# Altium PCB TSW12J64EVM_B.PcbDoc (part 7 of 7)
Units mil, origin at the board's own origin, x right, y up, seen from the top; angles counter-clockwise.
Board outline 8833 x 2680 mil, 10 copper layers (Top Layer L1, Gnd-Plane - L2, Signals - L3, Gnd-Plane - L4, Pwr Plane - L5, Signals - L6, Gnd-Plane - L7, Signals - L8, Gnd-Plane - L9, Bottom Layer - L10), stack 57.8 mil thick; 950 components, 533 nets, 2888 pads, 1732 vias.
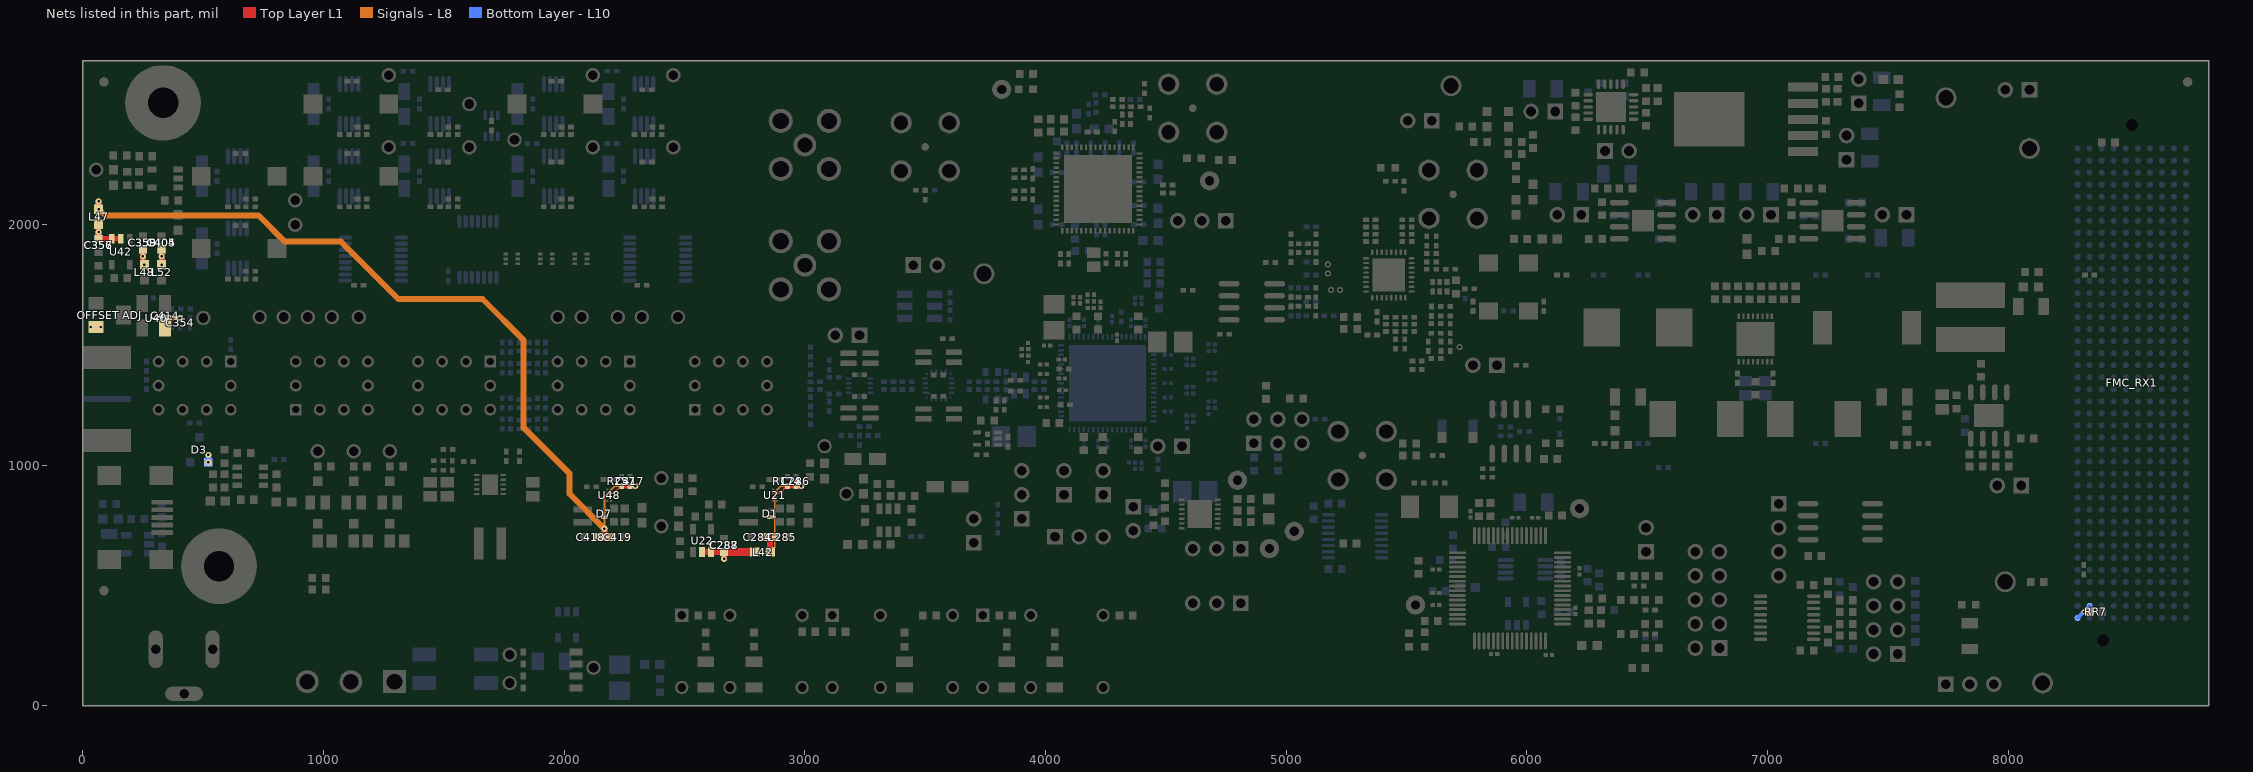
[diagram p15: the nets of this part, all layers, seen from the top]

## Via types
v1: diameter 18, hole 8, Top Layer L1 to Bottom Layer - L10, tented both sides, 1096 vias
v2: diameter 21.46, hole 10, Top Layer L1 to Bottom Layer - L10, tented both sides, 266 vias
v3: diameter 25, hole 10, Top Layer L1 to Bottom Layer - L10, tented both sides, 154 vias
v4: diameter 19.68, hole 7.87, Top Layer L1 to Bottom Layer - L10, 103 vias
v5: diameter 18, hole 8, Top Layer L1 to Bottom Layer - L10, tented bottom, 42 vias
v6: diameter 18, hole 8, Top Layer L1 to Bottom Layer - L10, tented top, 24 vias
v7: diameter 18, hole 8.01, Top Layer L1 to Bottom Layer - L10, tented both sides, 16 vias
v8: diameter 18, hole 8.01, Top Layer L1 to Bottom Layer - L10, tented bottom, 16 vias
v9: diameter 25.98, hole 12.99, Top Layer L1 to Bottom Layer - L10, tented top, 8 vias
v10: diameter 19.68, hole 7.87, Top Layer L1 to Bottom Layer - L10, tented top, 5 vias
v11: diameter 126, hole 106, Top Layer L1 to Bottom Layer - L10, tented top, 2 vias

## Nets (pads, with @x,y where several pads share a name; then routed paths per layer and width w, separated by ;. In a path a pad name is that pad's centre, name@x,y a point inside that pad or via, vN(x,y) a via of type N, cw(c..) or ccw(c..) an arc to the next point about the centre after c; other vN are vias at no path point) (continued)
VIO_-3: C404.1 C405.1 D3.1 L52.2 | length 155.5
  Top Layer L1 w24: v3(328,1832.91) v3(328,1867.4) C405.1@328,1895.65
  Bottom Layer - L10 w24: v3(328,1832.91) v3(328,1867.4) C404.1@328,1895.65
  Bottom Layer - L10 w25: v3(522.18,1012.5) v3(522.18,1042.5)
VIO_-3_LMH: "OFFSET ADJ.3" C354.1 C358.1 C359.1 C414.2 L48.2 U40.2 | length 268.1
  Top Layer L1 w21.46: C414.2@342,1569.82 360.6,1588.42 v2(360.6,1611) v2(405,1611)
  Top Layer L1 w24: C359.1@250,1895.65 v3(250,1867.4) 250,1838.9 v3(255.99,1832.91)
  Bottom Layer - L10 w15.75: v2(360.6,1611) v2(405,1611)
  Bottom Layer - L10 w24: C358.1@250,1895.65 v3(250,1867.4) 250,1838.9 v3(255.99,1832.91)
  other v2: 34.15,1573.79 75.68,1573.79
VIO_-3P25_1: C287.1 C288.1 L42.2 U22.2 U22.3 | length 276.5
  Top Layer L1 w24: v3(2665,610.51) C288.1@2665,638.76
  Top Layer L1 w25: U22.2@2573,638.76 U22.3@2610.4,638.76 C288.1@2665,638.76
  Top Layer L1 w31.5: C288.1@2665,638.76 L42.2@2793,638.76
  Bottom Layer - L10 w24: v3(2665,610.51) C287.1@2665,638.76
VIO_-3P25_2: C356.1 C357.1 L47.2 U42.2 U42.3 | length 180.7
  Top Layer L1 w23.62: C357.1@66,1940.13 U42.3@120.6,1940.13 U42.2@158,1940.13
  Top Layer L1 w24: C357.1@66,1940.13 v3(66,1968.38) L47.2@66,2000.57
  Bottom Layer - L10 w24: C356.1@66,1940.13 v3(66,1968.38)
VIO_-3P25V_1: C284.2 C285.2 C286.1 D1.2 L42.1 R174.2 U21.B2 | length 600.3
  Top Layer L1 w8: U21.B2@2883.86,882.9 2895.86,882.9 2925.3,912.34 R174.2@2927.99,912.34
  Top Layer L1 w19: R174.2@2927.99,912.34 C286.1@2962.99,912.34 v3(2985.33,912.34)
  Top Layer L1 w25: v3(2855.99,638.76) 2855.99,701.02
  Top Layer L1 w31.5: C284.2@2832.55,701.02 2855.99,701.02 C285.2@2879.43,701.02
  Signals - L8 w8: v3(2855.99,638.76) 2875,657.77 2875,888 2899.34,912.34 v3(2985.33,912.34)
VIO_-3P25V_2: C417.1 C418.2 C419.2 D7.2 L47.1 R257.2 U48.B2 | length 3463.1
  Top Layer L1 w8: U48.B2@2194.86,882.9 2206.86,882.9 2236.3,912.34 R257.2@2238.99,912.34
  Top Layer L1 w19: R257.2@2238.99,912.34 C417.1@2273.99,912.34 v3(2296.33,912.34)
  Top Layer L1 w24: v3(66,2063.56) v3(66,2095.74)
  Top Layer L1 w31.5: C418.2@2138.74,701.02 v3(2166.99,701.02) C419.2@2195.24,701.02
  Signals - L8 w8: v3(2166.99,736.02) 2166.99,868.99 2210.34,912.34 v3(2296.33,912.34)
  Signals - L8 w25: v3(66,2095.74) v3(66,2063.56) 92.56,2037 731,2037 840,1928 1073,1928 1311,1690 1661,1690 1832,1519 1832,1155 2023,964 2023,880.01 v3(2166.99,736.02) v3(2166.99,701.02)
VIO_B_M2C_RX: FMC_RX1.J39 FMC_RX1.K40 RR7.2 | length 93.2
  Top Layer L1 w18: v1(8313,390) RR7.2@8335.44,390
  Bottom Layer - L10 w18: FMC_RX1.K40@8288,365 v1(8313,390) FMC_RX1.J39@8338,415
pads on no net: 5VDC.3 "SH-Ts ADD1_1_2.0" FID1.1 FID2.1 FID3.1 FMC_RX1.401 FMC_RX1.402 FMC_RX1.A22 FMC_RX1.A23 FMC_RX1.A26 FMC_RX1.A27 FMC_RX1.A30 FMC_RX1.A31 FMC_RX1.A34 FMC_RX1.A35 FMC_RX1.A38 FMC_RX1.A39 FMC_RX1.B1 FMC_RX1.B4 FMC_RX1.B5 FMC_RX1.B8 FMC_RX1.B9 FMC_RX1.B20 FMC_RX1.B21 FMC_RX1.B24 FMC_RX1.B25 FMC_RX1.B28 FMC_RX1.B29 FMC_RX1.B32 FMC_RX1.B33 FMC_RX1.B36 FMC_RX1.B37 FMC_RX1.B40 FMC_RX1.C2 FMC_RX1.C3 FMC_RX1.C10 FMC_RX1.C11 FMC_RX1.C14 FMC_RX1.C15 FMC_RX1.C18 FMC_RX1.C19 FMC_RX1.C22 FMC_RX1.C23 FMC_RX1.C26 FMC_RX1.C27 FMC_RX1.D8 FMC_RX1.D9 FMC_RX1.D11 FMC_RX1.D12 FMC_RX1.D14 FMC_RX1.D15 FMC_RX1.D17 FMC_RX1.D18 FMC_RX1.D20 FMC_RX1.D21 FMC_RX1.D23 FMC_RX1.D24 FMC_RX1.D27 FMC_RX1.D29 FMC_RX1.D33 FMC_RX1.D34 FMC_RX1.E2 FMC_RX1.E3 FMC_RX1.E6 FMC_RX1.E7 FMC_RX1.E9 FMC_RX1.E10 FMC_RX1.E15 FMC_RX1.E16 FMC_RX1.E18 FMC_RX1.E19 FMC_RX1.E21 FMC_RX1.E22 FMC_RX1.E24 FMC_RX1.E25 FMC_RX1.E27 FMC_RX1.E28 FMC_RX1.E30 FMC_RX1.E31 FMC_RX1.E33 FMC_RX1.E34 FMC_RX1.E37 FMC_RX1.F4 FMC_RX1.F5 FMC_RX1.F7 FMC_RX1.F8 FMC_RX1.F10 FMC_RX1.F11 FMC_RX1.F13 FMC_RX1.F14 FMC_RX1.F16 FMC_RX1.F17 FMC_RX1.F19 FMC_RX1.F20 FMC_RX1.F22 FMC_RX1.F23 FMC_RX1.F25 FMC_RX1.F26 FMC_RX1.F28 FMC_RX1.F29 FMC_RX1.F31 FMC_RX1.F32 FMC_RX1.F34 FMC_RX1.F35 FMC_RX1.F37 FMC_RX1.F38 FMC_RX1.G2 FMC_RX1.G3 FMC_RX1.G15 FMC_RX1.G16 FMC_RX1.G18 FMC_RX1.G19 FMC_RX1.G21 FMC_RX1.G22 FMC_RX1.G24 FMC_RX1.G25 FMC_RX1.G28 FMC_RX1.G31 FMC_RX1.H1 FMC_RX1.H4 FMC_RX1.H5 FMC_RX1.H7 FMC_RX1.H8 FMC_RX1.H10 FMC_RX1.H11 FMC_RX1.H13 FMC_RX1.H14 FMC_RX1.H16 FMC_RX1.H17 FMC_RX1.H19 FMC_RX1.H20 FMC_RX1.H22 FMC_RX1.H23 FMC_RX1.H25 FMC_RX1.H26 FMC_RX1.H28 FMC_RX1.H29 FMC_RX1.H32 FMC_RX1.H35 FMC_RX1.J2 FMC_RX1.J3 FMC_RX1.J6 FMC_RX1.J7 FMC_RX1.J9 FMC_RX1.J10 FMC_RX1.J12 FMC_RX1.J13 FMC_RX1.J18 FMC_RX1.J19 FMC_RX1.J21 FMC_RX1.J22 FMC_RX1.J24 FMC_RX1.J25 FMC_RX1.J27 FMC_RX1.J28 FMC_RX1.J30 FMC_RX1.J31 FMC_RX1.J33 FMC_RX1.J34 FMC_RX1.J36 FMC_RX1.J37 FMC_RX1.K1 FMC_RX1.K4 FMC_RX1.K5 FMC_RX1.K7 FMC_RX1.K8 FMC_RX1.K10 FMC_RX1.K11 FMC_RX1.K13 FMC_RX1.K14 FMC_RX1.K16 FMC_RX1.K17 FMC_RX1.K19 FMC_RX1.K20 FMC_RX1.K22 FMC_RX1.K23 FMC_RX1.K25 FMC_RX1.K26 FMC_RX1.K31 FMC_RX1.K32 FMC_RX1.K34 FMC_RX1.K35 H3.0 H4.0 H5.1 H6.1 S1.3 SH-1V2ADC_INT_1_2.0 SH-1V2ADC_LDO_1_2.0 SH-1V9ADC_1_2.0 SH-1V9INT_1_2.0 SH-EXT5V_FMC12V_1_2.0 SH-FTDI_3P3V_1_2.0 SH-J2_1_2.0 SH-LMK_INT_1_2.0 SH-LMK_LDO_1_2.0 SH-LMX_INT_1_2.0 SH-LMX_LDO_1_2.0 SH-RSV_1_2.0 U3.1 U3.3 U3.4 U5.2 U5.7 U8.2 U8.7 U10.2 U10.3 U10.4 U10.9 U10.13 U10.14 U10.17 U13.21 U13.22 U13.23 U13.24 U13.30 U13.32 U13.33 U13.34 U13.36 U13.44 U13.45 U13.46 U13.55 U13.57 U13.58 U13.59 U13.60 U15.6 U15.7 U16.7 U17.4 U23. U27.10 U27.11 U29.10 U29.11 U40.3 U47.1 U47.3 USB.4 uWIRE.1 uWIRE.3 uWIRE.5 uWIRE.7 Vcmo_2_3.0
copper on no net:
  other v11: 8434,100 8434,2580

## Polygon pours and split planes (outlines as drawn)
VIO_3P3V_LMK_PLL on Signals - L8 "Signals - L8-VIO_3P3V_LMK_PLL" (solid, pour order 213): 4202,1924 4262,1924 4262,1995 4297,2030 4380,2030 4380,2277 6060,2277 6060,2353 4380,2353 4380,2497 4055,2497 4055,1974 4202,1974
VIO_3P3V_LMK_CLK on Signals - L8 "Signals - L8-VIO_3P3V_LMK_CLK" (solid, pour order 219): 4615,2153 6185,2153 6185,2661 3925,2660 3925,1871 4030,1871 4030,2522 4405,2522 4405,2378 6085,2378 6085,2252 4404,2252 4404,2025 4517,2025 4517,2097 4494,2097 4494,2197 4571,2197
VIO_4P05V on Signals - L3 "Signals - L3-VIO_4P05V" (solid, pour order 235): 8063,1400 8063,1695 6024,1695 6024,1400
VIO_1P9V on Signals - L3 "Signals - L3-VIO_1P9V" (solid, remove dead copper, pour order 211): 3991,2660 7554,2660 7554,2094 5866,2094 5866,2285 5533,2285 5533,2094 4213,2094 4213,1592 4290,1592 4290,944 4189,944 4189,1046 3863,1046 3863,1164 3991,1164
3P3V_FTDI on Signals - L3 "Signals - L3-3P3V_FTDI" (solid, remove dead copper, pour order 218): 4678,572 5163,572 5163,883 5452,883 5452,970 5739,970 5739,888 6211.89,887.9 6338.9,760.89 6339,476 6247,476 6247,451 5807,451 5807,540 6119,540 6119,793 6060,793 6060,739 5807,739 5807,783 5723,783 5723,451 5634,451 5634,377 6247,377 6247,476 6339,476 6339,389 6254,304 6253.9,167.11 6166.89,80.1 5777.11,80.1 5654,203 5513.21,203 5452.1,264.11 5452.1,443 4744,443 4744,393 4678,393
1P8V_USB on Signals - L3 "Signals - L3-1P8V_USB" (solid, remove dead copper, pour order 220): 5644,387 5644,441 5733,441 5733,773 5797,773 5797,729 6070,729 6070,783 6109,783 6109,550 5797,550 5797,441 6237,441 6237,387
VIO_3P3V_LMX on Signals - L3 "Signals - L3 - VIO_3P3V_LMX" (solid, remove dead copper, pour order 230): 5792,2043 5497,2043 5497,1954 5551,1954 5551,1777 5792,1777
VIO_3P3V_LMX on Signals - L3 "Signals - L3- VIO_3P3V_LMX" (solid, remove dead copper, pour order 229): 4942,2043 5355,2043 5355,1954 5071,1954 5071,1777 4942,1777
VIO_4P05V on Signals - L3 "Signals - L3-VIO_4P05V" (solid, remove dead copper, pour order 234): 4315,1366 4315,930 4164,930 4164,1032 3822,1032 3822,1884 2968,1884 2968,1129 1364,1129 1364,889 672,889 672,816 901,587 5098,587 5098,1366
3P3V_USB on Signals - L3 "Signals - L3-3P3V_USB" (solid, remove dead copper, pour order 217): 20,1029.9 401.03,1029.9 401.03,842.97 436,808 665,808 901,572 4644,572 4644,393 4579,393 4579,443 926,443 633,736 493,736 401.03,644.03 400.94,535.1 20,535.1
GND on Bottom Layer - L10 "Bottom Layer - L10-T2-GND" (solid, pour order 209): 3314,1545 3663,1545 3663,1574 3492,1574 3492,1645 3573,1645 3573,1675 3492,1675 3492,1745.91 3663,1745.91 3663,1774.91 3314,1774.91
GND on Bottom Layer - L10 "Bottom Layer - L10-U10-GND" (solid, pour order 208): 6285,2426 6421,2426 6421,2550 6285,2550 6270,2565 6238,2565 6238,2530 6285,2483
GND on Bottom Layer - L10 "Bottom Layer - L10-U6-GND" (solid, pour order 210): 4055,1989 4106,1989 4106,1978 4140,1978 4140,1985 4380,1985 4380,2310 4079,2310 4079,2305 4031,2305 4031,2273 4055,2273
5P0_12P0V_INT on Bottom Layer - L10 "Bottom Layer L10-12P0_INT" (solid, pour order 190): 6984,1405 6914,1405 6914,1327 6984,1327 6984,1405
GND on Bottom Layer - L10 "Bottom Layer L10-GND" (solid, pour order 224): 4980,2000 4980,1834 5097,1834 5097,2000
GND on Bottom Layer - L10 "Bottom Layer L10 - U4 G ND" (solid, pour order 223): 5357.34,1858.9 5357.34,1721.1 5495.13,1721.1 5495.13,1858.9
GND on Bottom Layer - L10 "Bottom Layer - L10 - Anolog In GND" (solid, remove dead copper, pour order 197): 20,2660 20,1040 411,1040 411,847 440,818 670,818 901,587 3853,587 3853,1227.31 3896.79,1271.1 4083.56,1270.78 4083.56,1389 3897,1389 3751,1535 3304,1535 3304,1670 662,1670 662,1788 461,1788 461,2660
VIO_-3P25V_2 on Top Layer L1 "Top Layer - L1-VIO_3P25V_2" (solid, pour order 201): 2180.66,792.02 2180.66,684.02 2152.66,684.02 2152.66,792.02 2180.66,792.02
NetC415_1 on Top Layer L1 "Top Layer - L10-NetC415_1" (solid, pour order 199): 2344,856.02 2189.99,856.02 2189.99,803.02 2344,803.02
NetD7_1 on Top Layer L1 "Top Layer - L1-NetD7_1" (solid, pour order 192): 2032,856.76 2184,856.76 2184,802.76 2032,802.76
Net+5_1 on Top Layer L1 "Top Layer L1- Net+5_1" (solid, pour order 233): 2022,188 2022,59 2154,59 2154,188
5P0_12P0V_INT on Top Layer L1 "Top Layer L1-5P0_12P0V_INT" (solid, remove dead copper, pour order 204): 1898,977 1842,977 1842,951 1795,904 1735,904 1735,894 1829,894 1842,907 1898,907
VIO_5V on Top Layer L1 "Top Layer L1-VIO_5V" (solid, remove dead copper, pour order 205): 1416,1028 1471,1028 1471,952 1541,952 1589,904 1649,904 1649,894 1555,894 1542,907 1416,907
NetL49_1 on Top Layer L1 "Top Layer L1-NetL49_1" (solid, remove dead copper, pour order 202): 1867,607 1867,751 1766,852 1766,885 1735,885 1735,800 1744,791 1744,741 1719,741 1719,607
NetL49_2 on Top Layer L1 "Top Layer L1-NetL49_2" (solid, remove dead copper, pour order 203): 1505,607 1505,739 1618,852 1618,885 1649,885 1649,800 1640,791 1640,741 1665,741 1665,607
NetD1_1 on Top Layer L1 "Top Layer - L1-NetD1_1" (solid, pour order 191): 2721,856.76 2873,856.76 2873,802.76 2721,802.76
GND on Top Layer L1 "Top Layer L1-U7-GND" (solid, pour order 221): 8169,1158 8169,1694 8125,1694 8125,1614 8004,1614 8004,1336 7982,1336 7982,1254 7698,1254 7698,1158 8090,1158 8090,1092 8123,1092 8123,1158
VIO_2P25V on Top Layer L1 "Top Layer L1- VIO_1P4V" (solid, pour order 231): 7559,1650 7638,1650 7638,1186 7559,1186 7559,1650
VIO_1P4V on Top Layer L1 "Top Layer L1- VIO_1P4V" (solid, pour order 232): 6387,1650 6235,1650 6235,1186 6387,1186 6387,1650
NetC169_2 on Top Layer L1 "Top Layer L1-NetC169_2" (solid, pour order 227): 6993,1442 7004,1442 7004,1405 7008,1405 7008,1353 7188,1353 7188,1650 7362,1650 7362,1276 7108,1276 7108,1115 6993,1115
NetC170_1 on Top Layer L1 "Top Layer L1-NetC170_1" (solid, pour order 228): 6905,1442 6894,1442 6894,1405 6890,1405 6890,1353 6710,1353 6710,1650 6536,1650 6536,1276 6790,1276 6790,1115 6905,1115
NetC168_1 on Top Layer L1 "Top Layer L1-NetC168_1" (solid, pour order 189): 6984,1643 6914,1643 6914,1704 6984,1704 6984,1643
GND on Top Layer L1 "Top Layer L1-U7-SW_GND" (solid, pour order 222): 7856,1346 7856,1453 7698,1453 7698,1346
5P0_12P0V_INT on Top Layer L1 "Top Layer L1-U7-12V_int" (solid, pour order 225): 7856,1269 7856,1336 7698,1336 7698,1269
VIO_4P05V on Top Layer L1 "Top Layer L1-VIO_3P6V" (solid, pour order 226): 8063,1624 8063,1720 8082,1720 8082,1758 7699,1758 7699,1653 8004,1653 8004,1624
5P0_12P0V_INT on Top Layer L1 "Top Layer L1-12P0_INT" (solid, pour order 207): 6984,1405 6914,1405 6914,1331 6984,1331 6984,1405
VIO_1P9V on Top Layer L1 "Top Layer L1-VIO_1P9V" (solid, remove dead copper, pour order 216): 4067,1301 4047,1301 4047,1297 4041,1291 4034,1291 4028,1297 4028,1363 4034,1369 4064,1369 4064,1320 4067,1320
Net1V2ADC_LDO_1 on Top Layer L1 "Top Layer L1-NetC172_1" (solid, pour order 214): 6273.68,2495 6273.68,2413 6297.68,2413 6297.68,2374 6234.68,2374 6234.68,2430 6084.68,2430 6084.68,2508 6219.68,2508 6219.68,2495
Net1V2ADC_INT_2 on Top Layer L1 "Top Layer L1-NetC172_1" (solid, pour order 215): 6423.68,2488 6423.68,2413 6393,2413 6393,2272 6463,2272 6463,2393 6512,2393 6512,2425 6462.68,2425 6462.68,2488
GND on Top Layer L1 "Top Layer L1-U2-GND" (solid, pour order 212): 4089,1179 4089,1303 4074,1303 4074,1368 4085,1368 4085,1430 4072,1430 4072,1447 4089,1447 4089,1527 4418,1527 4418,1179
GND on Top Layer L1 "Top Layer L1-U9 GND" (solid, pour order 188): 7144,1819 6201,1819 6201,1111 6337,1111 6337,1177 6225,1177 6225,1660 6397,1660 6397,1111 6447,1111 6447,1032 7118,1032 7118,1105 6984,1105 6984,1307.54 6914,1307.54 6914,1105 6780,1105 6780,1266 6526,1266 6526,1660 6719,1660 6720,1363 6855,1363 6855,1453 7043,1453 7043,1363 7178,1363 7178,1660 7372,1660 7372,1266 7118,1266 7118,1032 7499,1032 7499,1110 7549,1110 7549,1660 7648,1660 7648,1176 7609,1176 7609,1110 7672,1110 7673,1782 8042,1782 8042,1819 7144,1819 7144,1663 7064,1663 7043,1642 7043,1596 6855,1596 6855,1642 6834,1663 6754,1663 6754,1769 6812,1769 6812,1728 6942,1728 6942,1769 7004,1769 7004,1728 7086,1728 7086,1769 7144,1769
VIO_-3P25V_1 on Top Layer L1 "Top Layer - L1-VIO_3P25V_1" (solid, pour order 200): 2869.66,792.02 2869.66,684.02 2841.66,684.02 2841.66,792.02 2869.66,792.02
NetC282_1 on Top Layer L1 "Top Layer - L10-NetC282_1" (solid, pour order 198): 3033,856.02 2878.99,856.02 2878.99,803.02 3033,803.02
GND on Top Layer L1 "Top Layer - L1 - Anolog In GND" (solid, remove dead copper, pour order 206): 20,2660 20,1040.02 411,1039.92 411,847 440,818 670,818 901,587 3968,587 3968,1378 3810,1378 3810,1670 662,1670 662,1788 461,1788 461,2660
VIO_-1P25_U23 on Signals - L6 "Signals - L6 - L10-VIO_-1P25_U23" (solid, remove dead copper, pour order 193): 3127,841 2371,841 2371,587 3822,587 3822,1884 3416,1884 3416,977 3127,977
VIO_-1P25_U19 on Signals - L6 "Signals - L6 - L10-VIO_-1P25_U19" (solid, remove dead copper, pour order 196): 2371,1129 2371,851 3117,851 3117,987 3406,987 3406,1884 2968,1884 2968,1129
VIO_-3_LMH on Signals - L6 "Signals - L6 - L10-VIO_-3_LMH" (solid, remove dead copper, pour order 195): 311,2660 20,2660 20,1040 445,1040 445,1725 311,1725
VIO_-3 on Signals - L6 "Signals - L6 - L10-VIO_-3" (solid, remove dead copper, pour order 194): 461,2660 321,2660 321,1735 455,1735 455,1030 411,1030 411,847 440,818 662,818 662,1788 461,1788
GND2 on Gnd-Plane - L2 (split plane): 400.9,845 401.29,843.05 402.4,841.4 434.4,809.4 436.05,808.29 438,807.9 665.52,807.9 899.65,573.77 901.31,572.66 903.26,572.27 5158,572.27 5159.95,572.66 5161.6,573.77 5162.71,575.42 5163.1,577.37 5163.1,882.9 5447,882.9 5448.95,883.29 5450.6,884.4 5451.71,886.05 5452.1,888 5452.1,969.9 5738.9,969.9 5738.9,893 5739.29,891.05 5740.4,889.4 5742.05,888.29 5744,887.9 6211.89,887.9 6338.9,760.89 6338.9,389.11 6255.4,305.6 6254.29,303.95 6253.9,302 6253.9,167.11 6166.89,80.1 5777.11,80.1 5655.6,201.6 5653.95,202.71 5652,203.1 5513.11,203.1 5452.1,264.11 5452.1,438 5451.71,439.95 5450.6,441.6 5448.95,442.71 5447,443.1 926.11,443.1 634.6,734.6 632.95,735.71 631,736.1 495,736.1 493.05,735.71 491.4,734.6 402.4,645.6 401.29,643.95 400.9,642 400.9,535.1 20.1,535.1 20.1,1029.9 400.9,1029.9
GND on Gnd-Plane - L2 (split plane): 8812.9,20.1 20.1,20.1 20.1,524.9 406,524.9 407.95,525.29 409.6,526.4 410.71,528.05 411.1,530 411.1,639.89 497.11,725.9 628.89,725.9 920.39,434.4 922.05,433.29 922.44,433.21 924,432.9 5441.9,432.9 5441.9,262 5442.29,260.05 5443.4,258.4 5507.4,194.4 5509.05,193.29 5511,192.9 5649.89,192.9 5771.4,71.4 5773.05,70.29 5775,69.9 6169,69.9 6170.95,70.29 6172.6,71.4 6262.6,161.4 6263.71,163.05 6264.1,165 6264.1,299.89 6347.6,383.4 6348.71,385.05 6349.1,387 6349.1,763 6348.71,764.95 6347.6,766.6 6217.6,896.6 6215.95,897.71 6214,898.1 5749.1,898.1 5749.1,975 5748.71,976.95 5747.6,978.6 5745.95,979.71 5744,980.1 5447,980.1 5445.05,979.71 5443.4,978.6 5442.29,976.95 5441.9,975 5441.9,893.1 5158,893.1 5156.05,892.71 5154.4,891.6 5153.29,889.95 5152.9,888 5152.9,582.47 905.37,582.47 671.23,816.6 669.58,817.71 667.63,818.1 440.11,818.1 411.1,847.11 411.1,1035 410.71,1036.95 409.6,1038.6 407.95,1039.71 406,1040.1 20.1,1040.1 20.1,2659.9 8812.9,2659.9
GND on Gnd-Plane - L4 (split plane): 8812.9,20.1 20.1,20.1 20.1,2659.9 8812.9,2659.9
GND on Gnd-Plane - L7 (split plane): 8812.9,20.1 20.1,20.1 20.1,2659.9 8812.9,2659.9
GND on Gnd-Plane - L9 (split plane): 8812.9,20.1 20.1,20.1 20.1,2659.9 8812.9,2659.9
NetC158_1 on Pwr Plane - L5 (split plane): 8812.9,1995.1 7441.1,1995.1 7441.1,2419 7440.71,2420.95 7439.6,2422.6 7437.95,2423.71 7436,2424.1 7220,2424.1 7218.05,2423.71 7216.4,2422.6 7215.29,2420.95 7214.9,2419 7214.9,1995.1 6744.1,1995.1 6744.1,2659.9 8812.9,2659.9
VIO_1P4 on Pwr Plane - L5 (split plane): 6476.9,1045.1 6303.1,1045.1 6303.1,1990 6302.71,1991.95 6301.6,1993.6 6299.95,1994.71 6298,1995.1 6070.1,1995.1 6070.1,2659.9 6476.9,2659.9
VIO_2P25 on Pwr Plane - L5 (split plane): 7430.9,1184 7431.29,1182.05 7432.4,1180.4 7434.05,1179.29 7436,1178.9 7642.9,1178.9 7642.9,1045.1 7225.1,1045.1 7225.1,2413.9 7430.9,2413.9
VIO_1P2VA on Pwr Plane - L5 (split plane): 5873.9,2086.1 4209.04,2086.1 4207.09,2085.71 4205.43,2084.6 4115.4,1994.57 4114.29,1992.91 4113.9,1990.96 4113.9,1844.89 4114.29,1842.94 4115.4,1841.29 4178.9,1777.78 4178.9,1040.1 3832.1,1040.1 3832.1,1889 3831.71,1890.95 3830.6,1892.6 3828.95,1893.71 3827,1894.1 3416.1,1894.1 3416.1,2659.9 5873.9,2659.9
VIO_3P3V_LMX on Pwr Plane - L5 (split plane): 5010.9,1840 5011.29,1838.05 5012.4,1836.4 5014.05,1835.29 5016,1834.9 6139.45,1834.9 6139.45,1740 6139.84,1738.05 6140.95,1736.4 6142.6,1735.29 6144.55,1734.9 6182.45,1734.9 6182.45,1468.1 6035,1468.1 6033.05,1467.71 6031.4,1466.6 6030.29,1464.95 6029.9,1463 6029.9,1381.1 5961.1,1381.1 5961.1,1415 5960.71,1416.95 5959.6,1418.6 5957.95,1419.71 5956,1420.1 5474.11,1420.1 5377.6,1516.6 5375.95,1517.71 5374,1518.1 4814.1,1518.1 4814.1,1558 4813.71,1559.95 4812.6,1561.6 4810.95,1562.71 4809,1563.1 4754.1,1563.1 4754.1,1707.17 4935,1707.17 4936.95,1707.56 4938.6,1708.67 4939.71,1710.32 4940.1,1712.27 4940.1,1859.9 5010.9,1859.9
5P0_12P0V_INT on Pwr Plane - L5 (split plane): 6733.9,1990 6734.29,1988.05 6735.4,1986.4 6737.05,1985.29 6739,1984.9 7214.9,1984.9 7214.9,1040 7215.29,1038.05 7216.4,1036.4 7218.05,1035.29 7220,1034.9 7648,1034.9 7649.95,1035.29 7651.6,1036.4 7652.71,1038.05 7653.1,1040 7653.1,1184 7652.71,1185.95 7651.6,1187.6 7649.95,1188.71 7648,1189.1 7441.1,1189.1 7441.1,1984.9 8812.9,1984.9 8812.9,670.1 8638,670.1 8636.05,669.71 8634.4,668.6 8633.29,666.95 8632.9,665 8632.9,570.1 7890,570.1 7888.05,569.71 7886.4,568.6 7885.29,566.95 7884.9,565 7884.9,20.1 7795.1,20.1 7795.1,190 7794.71,191.95 7793.6,193.6 7791.95,194.71 7790,195.1 6572.1,195.1 6572.1,1040 6571.71,1041.95 6570.6,1043.6 6568.95,1044.71 6567,1045.1 6487.1,1045.1 6487.1,2659.9 6733.9,2659.9
12P0V_RX on Pwr Plane - L5 (split plane): 8812.9,20.1 7895.1,20.1 7895.1,559.9 8638,559.9 8639.95,560.29 8641.6,561.4 8642.71,563.05 8643.1,565 8643.1,659.9 8812.9,659.9
VIO_1P2VD on Pwr Plane - L5 (split plane): 6059.9,1995.1 5965,1995.1 5963.05,1994.71 5961.4,1993.6 5960.29,1991.95 5959.9,1990 5959.9,1945.1 5546,1945.1 5544.05,1944.71 5542.4,1943.6 5518.89,1920.1 4529,1920.1 4527.05,1919.71 4525.4,1918.6 4495.4,1888.6 4494.29,1886.95 4493.9,1885 4493.9,1710 4494.29,1708.05 4495.4,1706.4 4528.9,1672.89 4528.9,1245 4529.29,1243.05 4530.4,1241.4 4532.05,1240.29 4534,1239.9 5097.9,1239.9 5097.9,1040.1 4294,1040.1 4292.05,1039.71 4290.4,1038.6 4289.29,1036.95 4288.9,1035 4288.9,657.1 4189.1,657.1 4189.1,1779.89 4188.71,1781.84 4187.6,1783.5 4124.1,1847.01 4124.1,1988.85 4211.15,2075.9 5879,2075.9 5880.95,2076.29 5882.6,2077.4 5883.71,2079.05 5884.1,2081 5884.1,2659.9 6059.9,2659.9
VIO_3P3V on Pwr Plane - L5 (split plane): 6292.9,1040 6293.29,1038.05 6294.4,1036.4 6296.05,1035.29 6298,1034.9 6561.9,1034.9 6561.9,195.1 6349.1,195.1 6349.1,763 6348.71,764.95 6347.6,766.6 6217.6,896.6 6215.95,897.71 6214,898.1 5749.1,898.1 5749.1,975 5748.71,976.95 5747.6,978.6 5745.95,979.71 5744,980.1 5112,980.1 5110.05,979.71 5108.4,978.6 5107.29,976.95 5106.9,975 5106.9,587.1 4861.28,587.1 4859.33,586.71 4857.67,585.6 4856.57,583.95 4856.18,582 4856.18,381.1 4766.37,381.1 4766.37,582 4765.99,583.95 4764.88,585.6 4763.23,586.71 4761.28,587.1 3832.1,587.1 3832.1,1029.9 4178.9,1029.9 4178.9,652 4179.29,650.05 4180.4,648.4 4182.05,647.29 4184,646.9 4294,646.9 4295.95,647.29 4297.6,648.4 4298.71,650.05 4299.1,652 4299.1,1029.9 5103,1029.9 5104.95,1030.29 5106.6,1031.4 5107.71,1033.05 5108.1,1035 5108.1,1245 5107.71,1246.95 5106.6,1248.6 5104.95,1249.71 5103,1250.1 4539.1,1250.1 4539.1,1675 4538.71,1676.95 4537.6,1678.6 4504.1,1712.11 4504.1,1882.89 4531.11,1909.9 5521,1909.9 5522.95,1910.29 5524.6,1911.4 5548.11,1934.9 5965,1934.9 5966.95,1935.29 5968.6,1936.4 5969.71,1938.05 5970.1,1940 5970.1,1984.9 6292.9,1984.9
VIO_5V_LOGIC on Pwr Plane - L5 (split plane): 2957.9,1139.1 1359,1139.1 1357.05,1138.71 1355.4,1137.6 1354.29,1135.95 1353.9,1134 1353.9,899.1 1214.1,899.1 1214.1,1694.9 2410,1694.9 2411.95,1695.29 2413.6,1696.4 2414.71,1698.05 2415.1,1700 2415.1,2040.9 2957.9,2040.9
VIO_5V_LMC on Pwr Plane - L5 (split plane): 3405.9,1894.1 2968.1,1894.1 2968.1,2046 2967.71,2047.95 2966.6,2049.6 2964.95,2050.71 2963,2051.1 1059,2051.1 1057.05,2050.71 1055.4,2049.6 1054.29,2047.95 1053.9,2046 1053.9,899.1 672.1,899.1 672.1,1793 671.71,1794.95 670.6,1796.6 668.95,1797.71 667,1798.1 471.1,1798.1 471.1,2659.9 3405.9,2659.9
VIO_3P75_U19 on Pwr Plane - L5 (split plane): 3405.9,987.1 3122,987.1 3120.05,986.71 3118.4,985.6 3117.29,983.95 3116.9,982 3116.9,851.1 2371.1,851.1 2371.1,1128.9 2963,1128.9 2964.95,1129.29 2966.6,1130.4 2967.71,1132.05 2968.1,1134 2968.1,1883.9 3405.9,1883.9
VIO_5V_LMH on Pwr Plane - L5 (split plane): 310.9,1730 311.29,1728.05 312.4,1726.4 314.05,1725.29 316,1724.9 444.9,1724.9 444.9,1040.1 20.1,1040.1 20.1,2659.9 310.9,2659.9
VIO_5V_DRV on Pwr Plane - L5 (split plane): 2404.9,1705.1 1209,1705.1 1207.05,1704.71 1205.4,1703.6 1204.29,1701.95 1203.9,1700 1203.9,899.1 1064.1,899.1 1064.1,2040.9 2404.9,2040.9
VIO_3P75_U23 on Pwr Plane - L5 (split plane): 3821.9,1036.13 3821.68,1035 3821.9,1033.87 3821.9,587.1 2371.1,587.1 2371.1,840.9 3122,840.9 3123.95,841.29 3125.6,842.4 3126.71,844.05 3127.1,846 3127.1,976.9 3411,976.9 3412.95,977.29 3414.6,978.4 3415.71,980.05 3416.1,982 3416.1,1883.9 3821.9,1883.9
5VDC on Pwr Plane - L5 (split plane): 400.9,845 401.29,843.05 402.4,841.4 434.4,809.4 436.05,808.29 438,807.9 665.52,807.9 895.02,578.4 896.68,577.29 898.63,576.9 4756.18,576.9 4756.18,376 4756.57,374.05 4757.67,372.4 4759.33,371.29 4761.28,370.9 4861.28,370.9 4863.23,371.29 4864.88,372.4 4865.99,374.05 4866.37,376 4866.37,576.9 5112,576.9 5113.95,577.29 5115.6,578.4 5116.71,580.05 5117.1,582 5117.1,969.9 5738.9,969.9 5738.9,893 5739.29,891.05 5740.4,889.4 5742.05,888.29 5744,887.9 6211.89,887.9 6338.9,760.89 6338.9,190 6339.29,188.05 6340.4,186.4 6342.05,185.29 6344,184.9 7784.9,184.9 7784.9,20.1 20.1,20.1 20.1,1029.9 400.9,1029.9
VIO_3 on Pwr Plane - L5 (split plane): 460.9,1793 461.29,1791.05 462.4,1789.4 464.05,1788.29 466,1787.9 661.9,1787.9 661.9,818.1 440.11,818.1 411.1,847.11 411.1,1029.9 450,1029.9 451.95,1030.29 453.6,1031.4 454.71,1033.05 455.1,1035 455.1,1730 454.71,1731.95 453.6,1733.6 451.95,1734.71 450,1735.1 321.1,1735.1 321.1,2659.9 460.9,2659.9
VIO_5V on Pwr Plane - L5 (split plane): 2360.9,587.1 900.74,587.1 672.1,815.74 672.1,888.9 1359,888.9 1360.95,889.29 1362.6,890.4 1363.71,892.05 1364.1,894 1364.1,1128.9 2360.9,1128.9

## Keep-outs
Keep-Out Layer:
  text ".Layer_Name" at 601,-858.49 h60

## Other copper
Top Layer L1:
  text ".Layer_Name" at 601,-858.49 h60
Signals - L3:
  text ".Layer_Name" at 601,-858.49 h60
Signals - L6:
  text ".Layer_Name" at 601,-858.49 h60
Signals - L8:
  text ".Layer_Name" at 601,-858.49 h60
Bottom Layer - L10:
  text ".Layer_Name" at 601,-858.49 h60
Gnd-Plane - L9 (plane layer: these items are gaps in the copper):
  lines w21.46: 3212.49,1315.42 3241.95,1344.89 ; 3212.49,1344.89 3241.95,1315.42
  text ".Layer_Name" at 601,-858.49 h60
Gnd-Plane - L7 (plane layer: these items are gaps in the copper):
  lines w21.46: 3212.49,1315.42 3241.95,1344.89 ; 3212.49,1344.89 3241.95,1315.42
  text ".Layer_Name" at 601,-858.49 h60
Gnd-Plane - L4 (plane layer: these items are gaps in the copper):
  lines w21.46: 3212.49,1315.42 3241.95,1344.89 ; 3212.49,1344.89 3241.95,1315.42
  text ".Layer_Name" at 601,-858.49 h60
  text ".Layer_Name" at 601,-858.49 h60
Gnd-Plane - L2 (plane layer: these items are gaps in the copper):
  lines w10: 0,530 406,530 406,642 495,731 631,731 924,438 5447,438 5447,262 5511,198 5652,198 5775,75 6169,75 6259,165 6259,302 6344,387 6344,763 6214,893 5744,893 5744,975 5447,975 5447,888 5158,888 5158,577.37 903.26,577.37 667.63,813 438,813 406,845 406,1035 0,1035
  lines w21.46: 3212.49,1315.42 3241.95,1344.89 ; 3212.49,1344.89 3241.95,1315.42
  text ".Layer_Name" at 601,-858.49 h60
Pwr Plane - L5 (plane layer: these items are gaps in the copper):
  rectangle: 1676.94,804.88 1707.06,835
  lines w10: 0,1035 450,1035 450,1730 316,1730 316,2680 ; 406,1035 406,845 438,813 667.63,813 898.63,582 4761.28,582 4761.28,376 4861.28,376 4861.28,582 5112,582 5112,975 5744,975 5744,893 6214,893 6344,763 6344,190 7790,190 7790,0 ; 466,2680 466,1793 667,1793 667,813 ; 667,894 1359,894 1359,1134 2963,1134 2963,2046 1059,2046 1059,894 ; 1209,894 1209,1700 2410,1700 2410,2046 ; 2366,582 2366,1134 ; 2366,846 2960,846 3122,846 3122,982 3411,982 3411,2680 ; 2963,1889 3827,1889 3827,582 ; 3826.78,1035 4184,1035 ; 5879,2680 5879,2081 4209.04,2081 4119,1990.96 4119,1844.89 4184,1779.89 4184,652 4294,652 4294,1035 5103,1035 5103,1245 4534,1245 4534,1675 4499,1710 4499,1885 4529,1915 5521,1915 5546,1940 5965,1940 5965,1990 6298,1990 6298,1040 6482,1040 ; 6065,1990 6065,2680 ; 6482,2680 6482,1040 ; 6567,190 6567,1040 6482,1040 ; 6739,2680 6739,1990 7220,1990 ; 7436,1990 8833,1990 ; 7890,0 7890,565 8638,565 8638,665 8833,665 ; 4749,1558 4749,1712.27 4935,1712.27 4935,1865 5016,1865 5016,1840 6144.55,1840 6144.55,1740 6187.55,1740 6187.55,1463 6035,1463 6035,1376 5956,1376 5956,1415 5472,1415 5374,1513 4809,1513 4809,1558 4749,1558 ; 7220,1040 7648,1040 7648,1184 7436,1184 7436,2419 7220,2419 7220,1040
  text ".Layer_Name" at 601,-858.49 h60

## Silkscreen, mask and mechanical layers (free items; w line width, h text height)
Top Overlay:
  region: 5465,257 5165,257 5165,157 5465,157
  text ".PCB_Rev" at 8453,1225 h60 r90
  text ".PRJ_Title" at 8463,511 h60 r90
  text ".PRJ_Number" at 4557,177.01 h60
  text ".PCB_Rev" at 5007,177.01 h60
  text "-" at 5095,177.01 h60
  text ".Layer_Name" at 601,-858.49 h60
Bottom Overlay:
  text "CAUTION HOT SURFACE" at 5697,1322 h40
  text ".Layer_Name" at 601,-858.49 h60
Top Paste:
  text ".Layer_Name" at 601,-858.49 h60
Bottom Paste:
  text ".Layer_Name" at 601,-858.49 h60
Top Solder:
  text ".Layer_Name" at 601,-858.49 h60
  text ".Layer_Name" at 601,-858.49 h60
Bottom Solder:
  lines w10.7: 3063.39,1314.47 3069.23,1308.63 3088.94,1308.63 3101.86,1295.71 ; 3063.39,1345.84 3069.23,1351.68 3088.94,1351.68 3101.86,1364.61 ; 3101.86,1297.24 3124.94,1320.31 3181.94,1320.31 ; 3101.86,1363.08 3124.94,1340 3181.94,1340
  lines w12: 4001.69,1322.16 4062.63,1322.16 ; 4001.69,1338.16 4062.63,1338.16
  lines w14: 188,1275 348,1115 484.68,1115 484.68,1175.16 560,1175.16 615,1230.16 ; 265,1430.16 315,1430.16 ; 315,1230.16 370,1175.16 445.31,1175.16 ; 415,1230.16 466,1281.16 699,1281.16 ; 515,1430.16 566,1379.16 699,1379.16 ; 615,1430.16 615,1481.31 ; 700,1280.16 801,1179.16 934,1179.16 985,1230.16 ; 700,1380.16 801,1481.16 1034,1481.16 1085,1430.16 ; 885,1230.16 936,1281.16 1442,1281.16 1493,1230.16 ; 885,1430.16 936,1379.16 1542,1379.16 1593,1430.16 ; 1185,1230.16 1303.84,1111.31 2424.16,1111.31 2543,1230.16 ; 1185,1430.16 1303.84,1549 2424.16,1549 2543,1430.16 ; 1393,1230.16 1472,1151.16 1743,1151.16 1777,1151.16 1813.32,1151.16 1813.31,1185.31 ; 1393,1430.16 1472,1509.16 1743,1509.16 1777,1509.16 1813.32,1509.16 1813.31,1475 ; 1693,1230.16 1743,1230.16 ; 1693,1430.16 1743,1430.16 ; 1743,1237.97 1777,1237.97 1813.32,1237.97 1813.31,1272.12 ; 1743,1422.34 1777,1422.34 1813.32,1422.34 1813.31,1388.19 ; 1852.68,1185.31 1852.68,1151.16 1889,1151.16 1923,1151.16 2194,1151.16 2273,1230.16 ; 1852.68,1272.12 1852.68,1237.97 1889,1237.97 1923,1237.97 ; 1852.68,1388.19 1852.68,1422.34 1889,1422.34 1923,1422.34 ; 1852.68,1475 1852.68,1509.16 1889,1509.16 1923,1509.16 2194,1509.16 2273,1430.16 ; 1923,1230.16 1973,1230.16 ; 1923,1430.16 1973,1430.16 ; 2073,1230.16 2124,1281.16 2792,1281.16 2843,1230.16 ; 2173,1430.16 2224,1379.16 2792,1379.16 2843,1430.16 ; 2643,1230.16 2694,1179.16 2863,1179.16 2998.32,1314.47 3024.02,1314.47 3024.02,1282.69 ; 2743,1430.16 2794,1481.16 2863,1481.16 2998.32,1345.84 3024.02,1345.84 3024.02,1377.63 ; 3272.5,1320.31 3322.87,1320.31 3328.71,1314.47 ; 3272.5,1340 3322.87,1340 3328.71,1345.84 ; 3368.08,1314.47 3406.18,1314.47 ; 3368.08,1345.84 3405.18,1345.84 ; 3450.39,1320.32 3500.76,1320.32 ; 3450.39,1340 3500.76,1340 ; 3611,1320.32 3683.63,1320.32 ; 3611,1340 3683.63,1340 ; 3723,1314.47 3757.31,1314.47 ; 3723,1345.84 3757.31,1345.84 ; 3750.92,1273.02 3750.92,1314.47 ; 3750.92,1345.84 3750.92,1387.3 ; 3803.08,1273.47 3836,1273.47 ; 3805.54,1384.84 3836,1384.84 ; 3836,1280.39 3868.8,1280.39 ; 3836,1379.92 3868.8,1379.92 ; 3919.2,1312.55 3952.71,1312.55 ; 3919.2,1347.76 3952.71,1347.76
  text ".Layer_Name" at 601,-858.49 h60
Drill Guide:
  text ".Layer_Name" at 601,-858.49 h60
M1 Board Outline:
  the board outline again, w10
  text ".Layer_Name" at 601,-858.49 h60
M2 Board Dimensions:
  rectangle: 23.5,-285.5 148.5,-160.5
  rectangle: 148.5,-410.5 523.5,-285.5
  lines w7: 23.5,-285.5 1023.5,-285.5 ; 148.5,-410.5 148.5,-160.5 ; 273.5,-410.5 273.5,-160.5 ; 523.5,-410.5 523.5,-160.5 ; 773.5,-410.5 773.5,-160.5 ; 23.5,-410.5 1023.5,-410.5 1023.5,-160.5 23.5,-160.5 23.5,-410.5
  lines w10: 23.5,-475.5 23.5,-455.5 ; 83.5,-485.5 23.5,-465.5 ; 83.5,-445.5 23.5,-465.5 ; 247.58,-465.5 23.5,-465.5 ; 799.42,-465.5 1023.5,-465.5 ; 963.5,-485.5 1023.5,-465.5 ; 963.5,-445.5 1023.5,-465.5 ; 1023.5,-475.5 1023.5,-455.5
  text "1000 (mil)" at 257.58,-501.49 h60
  text ".Layer_Name" at 601,-858.49 h60
M3 3D STEP Top:
  text ".Layer_Name" at 601,-858.49 h60
M4 3D STEP Bottom:
  text ".Layer_Name" at 601,-858.49 h60
M5 Assembly Top:
  lines w10: -268,-930.17 6332,-930.17 ; -268,-726.83 6334,-726.83 ; -268,-523.5 -268,-1133.5 3737,-1133.5 6334,-1133.5 6334,-523.5 -267.5,-523.5 -267.5,-1133.5 1308,-1133.5 ; 2197,-1133.5 2197,-523.5 ; 3464,-726.83 3464,-523.5 ; 4304,-726.83 4304,-523.5 ; 4926,-1140 4926,-937.17
  text "K1 - K5  Body to be mounted approxiamtely 0.025 inches above PC board" at 9024,2100 h60
  text "but cannot be in contact with the PC board" at 9024,2000 h60
  text "COMPONENTS MARKED 'DNP' SHOULD NOT BE POPULATED, AND MAY NOT BE IN BILL OF MATERIALS" at 1177.5,-318.5 h60
  text "ASSEMBLY VARIANT:" at 1177,-434 h60
  text ".VariantName" at 2213,-434 h60
  text "PCB VIEWED FROM TOP SIDE" at -204.5,-655.67 h60
  text "BOARD #:" at 2272,-655.67 h60
  text ".PRJ_Number" at 2817.5,-655.67 h60
  text "REV:" at 3662,-655.67 h60
  text ".PCB_Rev" at 3953.5,-655.67 h60
  text "SVN REV:" at 4500,-655.67 h60
  text ".VersionControl_RevNumber" at 5006,-655.67 h60
  text "IGNORE ->" at -204.5,-858.49 h60
  text "PLOT NAME =" at -204.5,-1064.34 h60
  text ".plot_File_Name" at 601,-1064.34 h60
  text "GENERATED    :" at 2274,-1064.34 h60
  text ".Print_Date" at 3143.5,-1064.34 h60
  text ".Print_Time" at 3872.5,-1064.34 h60
  text "TEXAS INSTRUMENTS" at 5137,-1064.34 h60
M6 Assembly Bottom:
  lines w10: -268.5,-727.33 6333.5,-727.33 ; -266.5,-930.67 6333.5,-930.67 ; 1139.5,-1140.5 1139.5,-937.67 ; 1761.5,-727.33 1761.5,-524 ; 2601.5,-727.33 2601.5,-524 ; 3868.5,-1134 3868.5,-524 ; 4757.5,-1134 6333,-1134 6333,-524 -268.5,-524 -268.5,-1134 2328.5,-1134 6333.5,-1134 6333.5,-524
  text "COMPONENTS MARKED 'DNP' SHOULD NOT BE POPULATED, AND MAY NOT BE IN BILL OF MATERIALS" at 6126,-318 h60
  text ".VariantName" at 5082,-434 h60
  text "ASSEMBLY VARIANT:" at 6121,-434 h60
  text ".VersionControl_RevNumber" at 1059.5,-656.17 h60
  text "SVN REV:" at 1565.5,-656.17 h60
  text ".PCB_Rev" at 2112,-656.17 h60
  text "REV:" at 2403.5,-656.17 h60
  text ".PRJ_Number" at 3248,-656.17 h60
  text "BOARD #:" at 3793.5,-656.17 h60
  text "PCB VIEWED FROM BOTTOM SIDE" at 6270,-656.17 h60
  text "IGNORE ->" at 2571.85,-858.49 h60
  text "TEXAS INSTRUMENTS" at 928.5,-1064.84 h60
  text ".Print_Time" at 2193,-1064.84 h60
  text ".Print_Date" at 2922,-1064.84 h60
  text "GENERATED    :" at 3791.5,-1064.84 h60
  text ".plot_File_Name" at 5464.5,-1064.84 h60
  text "PLOT NAME =" at 6270,-1064.84 h60
M9 Title Sheet:
  drawing of 57 lines, arcs and shapes, not listed
  text "1" at 763.84,8036.5 h70
  text "2" at 3259.5,8036.5 h70
  text "3" at 5748.84,8036.5 h70
  text "4" at 8255.51,8036.5 h70
  text "5" at 10754.5,8036.5 h70
  text "6" at 13259.5,8036.5 h70
  text "A" at -392.5,6893.5 h70
  text "A" at 14407.5,6893.5 h70
  text "B" at -392.5,4513.5 h70
  text "B" at 14407.5,4513.5 h70
  text "C" at -392.5,2138.5 h70
  text "C" at 14407.5,2138.5 h70
  text "PROJECT TITLE:" at 11367.5,277.5 h45
  text ".PRJ_Title" at 11417.5,144.17 h70
  text "DESIGNED FOR:" at 11367.5,-23.5 h45
  text ".PRJ_Customer" at 11417.5,-163.5 h70
  text "D" at -392.5,-231.5 h70
  text "D" at 14407.5,-231.5 h70
  text "FILE NAME:" at 11367.5,-323.5 h45
  text ".PCB_File_Name_No_Path" at 11417.5,-443.5 h70
  text "Texas Instruments (TI) and/or its licensors do not warrant the accuracy or completeness of this specification" at 6398,-605.34 h45
  text "ENGINEER:" at 11367.5,-613.5 h45
  text "LAYOUT BY:" at 12872.5,-613.5 h45
  text "or any information contained therein. TI and/or its licensors do not warrant that this design will meet" at 6353.01,-718 h45
  text ".PRJ_Engineer" at 11417.5,-768.49 h70
  text ".PCB_Layout" at 12923,-768.49 h70
  text "the specifications, will be suitable for your application or fit for any particular purpose, or will operate in" at 6353.01,-830.67 h45
  text ".Layer_Name" at 601,-858.49 h60
  text "ALTIUM DESIGNER VERSION:" at 12872.5,-923.5 h45
  text "an implementation. TI and/or its licensors do not warrant that the design is production worthy. You should" at 6353.01,-943.33 h45
  text "completely validate and test your design implementation to confirm the system functionality for your application." at 6398,-1056 h45
  text ".print_Scale" at 11417.5,-1056.83 h70
  text ".Application_BuildNumber" at 12923,-1056.83 h70
  text "1" at 763.84,-1263.5 h70
  text "2" at 3259.5,-1263.5 h70
  text "3" at 5748.84,-1263.5 h70
  text "4" at 8255.51,-1263.5 h70
  text "5" at 10754.5,-1263.5 h70
  text "6" at 13259.5,-1263.5 h70
M10 Fab Notes:
  drawing of 207 lines, arcs and shapes, not listed
  text "DESIGN INFORMATION" at 12405.02,6810 h60
  text "(REFER ALSO ARRAY/PANEL PROFILING INFORMATION)" at 12043.46,6648.29 h60
  text "BOARD SIZE" at 11357.46,6644 h60
  text "X" at 12325.46,6516.18 h60
  text "Number of Layers :" at 11760.46,6319 h60
  text "10" at 12855.27,6309 h60
  text "MIN. TRACK WIDTH:" at 11760.46,6180 h60
  text "4" at 12856.7,6180 h60
  text "MIL" at 13011.46,6180 h60
  text "MIN. CLEARANCE:" at 11760.46,6048 h60
  text "4" at 12856.7,6048 h60
  text "MIL" at 13011.46,6048 h60
  text "MIN. VIA PAD SIZE:" at 11760.46,5916 h60
  text "18" at 12826.71,5916 h60
  text "MIL" at 13011.46,5916 h60
  text "0.05mm (2MIL)" at 12455.46,5774.29 h60
  text "MINIMUM ANNULAR RING" at 11431.23,5770 h60
  text "EXTERNAL" at 13163.46,5770 h60
  text "PER" at 11631.23,5652 h60
  text "IPC-D-275 CLASS 2 LEVEL C" at 11851.23,5652 h60
  text "MIL, HOLES" at 13339.46,5539.71 h60
  text "+/-" at 12947,5539 h60
  text "+/-" at 13801,5539 h60
  text "REGISTRATION TOLERANCES:" at 11431.23,5534 h60
  text "METAL" at 12631,5534 h60
  text "5" at 13207.2,5534 h60
  text "3" at 14040.2,5534 h60
  text "MIL" at 14156.46,5534 h60
  text "MATERIAL:" at 11356.46,5324.54 h60
  text "FR-4 High Tg" at 12342.9,5184.21 h60
  text "FR-4" at 11817.46,5175.64 h60
  text "X" at 13078.46,5176 h60
  text "OTHER SEE LAYER STACK UP" at 13265.46,5175.64 h50
  text "62 MIL (1.6mm) +/-10%" at 12097.56,5012.92 h60
  text "THICKNESS:" at 11431.23,5008.64 h60
  text "X" at 11969.4,5008.64 h60
  text "OTHER" at 13382.46,5008.64 h60
  text "TOLERANCE:" at 11431.23,4850.64 h60
  text "X" at 12270.53,4850.64 h60
  text "ANSI IPC-6012 TYPE 3 CLASS 2" at 12457.48,4850.64 h60
  text "OTHER +/-" at 12457.46,4694.64 h60
  text "BOW & TWIST:" at 11431.23,4537.64 h60
  text "X" at 12270.53,4537.64 h60
  text "ANSI IPC-6012 TYPE 3 CLASS 2" at 12457.48,4537.64 h60
  text "OTHER +/-" at 12457.46,4379.13 h60
  text "COPPER THICKNESS (FINISHED):" at 11356.46,4243.64 h60
  text "0.7MIL (0.5oz)" at 12236.46,4090.92 h60
  text "1.4MIL (1oz)" at 13003.46,4090.92 h60
  text "2.8MIL (2oz)" at 13730.46,4090.92 h60
  text "OUTER:" at 11713.46,4086.64 h60
  text "X" at 12108,4086 h60
  text "0.7MIL (0.5oz)" at 12236.46,3933.92 h60
  text "2.8MIL (2oz)" at 13003.46,3933.92 h60
  text "N/A" at 13730,3934.29 h60
  text "INNER SIGNAL:" at 11424.38,3929.64 h60
  text "X" at 12109.42,3929.64 h60
  text "X" at 12876.42,3929.64 h60
  text "DRILLING:" at 11356.46,3790.64 h60
  text "REFERENCE:" at 11431.23,3673.64 h60
  text "X" at 12079.46,3673.64 h60
  text "AS SHOWN" at 12266.46,3673.64 h60
  text "X" at 12980.46,3673.64 h60
  text "NC_DRILL FILES" at 13117.46,3673.64 h60
  text "PTH MIN COPPER THICKNESS:" at 11431.23,3515.64 h60
  text "X" at 12781.46,3515.64 h60
  text "1MIL" at 12918.46,3515.64 h60
  text "OTHER" at 13415.46,3515.64 h60
  text "BOARD FINISH:" at 11356.46,3356.64 h60
  text "SILKSCREEN:" at 11511.68,3238.64 h60
  text "X" at 12460.46,3238.64 h60
  text "TOP" at 12586.46,3238.64 h60
  text "X" at 12970.46,3238.64 h60
  text "BOTTOM" at 13097.46,3238.64 h60
  text "SILKSCREEN COLOR:" at 11511.68,3071.64 h60
  text "X" at 12459.42,3071.64 h60
  text "WHITE" at 12586.46,3071.64 h60
  text "OTHER" at 13097.46,3071.64 h60
  text "SOLDER RESIST COLOR:" at 11511.68,2901.64 h60
  text "X" at 12079.42,2742.44 h60
  text "GREEN" at 12206.46,2742.44 h60
  text "BLUE" at 12797.46,2742.44 h60
  text "OTHER" at 13335.46,2742.44 h60
  text "IMMERSION GOLD (ENIG)" at 12417.46,2553.92 h60
  text "SURFACE FINISH:" at 11356.46,2549.64 h60
  text "X" at 12230.51,2549.64 h60
  text "IMM. TIN/SILVER OR EQUIV" at 11686,2392.64 h60
  text "OTHER" at 13117.46,2392.64 h60
  text "ARRAY/PANEL:" at 11356.46,2213.64 h60
  text "CUT AND TRIM PER MECH LAYER 1" at 12417.46,2209.35 h60
  text "N.C. ROUTE" at 12417.46,2057.64 h60
  text "X" at 13096.46,2057.64 h60
  text "V. SCORE" at 13283.46,2057.64 h60
  text "CERTIFICATION:" at 11356.46,1920.64 h60
  text "MATERIALS AND WORKMANSHIP FOR ALL PCBS" at 12081.46,1920.64 h60
  text "TO MEET OR EXCEED THE REQUIREMENTS OF:" at 12081.46,1822.64 h60
  text "X" at 11707.96,1686.13 h60
  text "ANSI IPC-A-600F CLASS ->" at 11846.96,1686.13 h60
  text "X" at 13486.02,1686.13 h60
  text "2" at 13604.96,1686.14 h60
  text "1" at 13289.96,1684.64 h60
  text "3" at 13958.96,1684.64 h60
  text "X" at 11710.02,1526.64 h60
  text "UL 94V-0" at 11846.96,1526.64 h60
  text "X" at 12522.02,1526.64 h60
  text "RoHS" at 12658.96,1526.64 h60
  text "OTHER" at 13303.36,1526.64 h60
  text "PER ORDER" at 13700.42,1526.64 h60
  text "ADDITIONAL REQUIREMENTS:" at 11356.46,1385.64 h60
  text "MICROSECTION:" at 11431.23,1270.64 h60
  text "YES" at 12336.96,1270.64 h60
  text "REQUIRED" at 13198.46,1114.49 h60
  text "BARE BOARD ELEC. TEST:" at 11431.23,1111.64 h60
  text "NONE" at 12736.96,1111.64 h60
  text "X" at 13071.46,1111.64 h60
  text "PER ORDER" at 13790.46,1111.64 h60
  text "MANUFACTURER'S ID/LOGO:" at 11431.23,954.64 h60
  text "RAIL" at 12896.96,950.35 h60
  text "X" at 13271.46,950.35 h60
  text "METAL" at 13388.77,950.35 h60
  text "SILK" at 13900.46,950.35 h60
  text ".Layer_Name" at 601,-858.49 h60
M11 Gerber Information:
  lines w10: -268,-930.17 6332,-930.17 ; -268,-726.83 6334,-726.83 ; -268,-523.5 -268,-1133.5 3737,-1133.5 6334,-1133.5 6334,-523.5 -267.5,-523.5 -267.5,-1133.5 1308,-1133.5 ; 2197,-1133.5 2197,-523.5 ; 3464,-726.83 3464,-523.5 ; 4304,-726.83 4304,-523.5 ; 4926,-1140 4926,-937.17
  text "ALL ARTWORK VIEWED FROM TOP SIDE" at -204.5,-655.67 h60
  text "BOARD #:" at 2272,-655.67 h60
  text ".PRJ_Number" at 2817.5,-655.67 h60
  text "REV:" at 3662,-655.67 h60
  text ".PCB_Rev" at 3953.5,-655.67 h60
  text "SVN REV:" at 4500,-655.67 h60
  text ".VersionControl_RevNumber" at 5006,-655.67 h60
  text "LAYER NAME =" at -204.5,-858.49 h60
  text "PLOT NAME =" at -204.5,-1064.34 h60
  text ".plot_File_Name" at 601,-1064.34 h60
  text "GENERATED    :" at 2274,-1064.34 h60
  text ".Print_Date" at 3143.5,-1064.34 h60
  text ".Print_Time" at 3872.5,-1064.34 h60
  text "TEXAS INSTRUMENTS" at 5137,-1064.34 h60
M12 Stackup:
  lines w11: 4936,4388 4149,6075 4936,7762
  lines w12: 5042.02,7259.85 11217.98,7259.85 ; 5042.02,7472.75 11217.98,7472.75 ; 4979,4449 ccw(c5048,4449) 5048,4380 11212,4380 ccw(c11212,4449) 11281,4449 11281,7692 ccw(c11212,7692) 11212,7761 5048,7761 ccw(c5048,7692) 4979,7692 4979,4449
  text "Layer Stack Up Detail for: TSW12J64EVM_B.PcbDoc" at 5042.02,7534.88 h110
  text "Layer" at 5042.02,7393.25 h49
  text "Gerber" at 6382.46,7393.25 h49
  text "Copper" at 7040.09,7393.25 h49
  text "Dielectric" at 7777.73,7393.25 h49
  text "Dielectric" at 8549.66,7393.25 h49
  text "Dielectric" at 9533.72,7393.25 h49
  text "Dielectric" at 10305.65,7393.25 h49
  text "Name" at 5042.02,7295.25 h49
  text "Document" at 6382.46,7295.25 h49
  text "Thickness" at 7040.09,7295.25 h49
  text "Height" at 7777.73,7295.25 h49
  text "Material" at 8549.66,7295.25 h49
  text "Constant" at 9533.72,7295.25 h49
  text "Type" at 10305.65,7295.25 h49
  text "Top Solder Mask" at 5042.02,7142.44 h69
  text "(.GTS)" at 6382.46,7142.44 h69
  text "0.4mil" at 7777.73,7142.44 h69
  text "Solder Resist" at 8549.66,7142.44 h69
  text "3.50" at 9533.72,7142.44 h69
  text "Top Layer L1" at 5042.02,6919.62 h69
  text "(.GTL)" at 6382.46,6919.62 h69
  text "0.6mil" at 7040.09,6919.62 h69
  text "4mil" at 7777.73,6808.21 h69
  text "Rogers RO4350" at 8549.66,6808.21 h69
  text "3.66" at 9533.72,6808.21 h69
  text "Core" at 10305.65,6808.21 h69
  text "Gnd-Plane - L2" at 5042.02,6696.8 h69
  text "(.GP1)" at 6382.46,6696.8 h69
  text "1.2mil" at 7040.09,6696.8 h69
  text "6.7mil" at 7777.73,6585.39 h69
  text "Isola 370HR" at 8549.66,6585.39 h69
  text "4.11" at 9533.72,6585.39 h69
  text "PrePreg" at 10305.65,6585.39 h69
  text "Signals - L3" at 5042.02,6473.98 h69
  text "(.G1)" at 6382.46,6473.98 h69
  text "0.6mil" at 7040.09,6473.98 h69
  text "6mil" at 7777.73,6362.57 h69
  text "Isola 370HR" at 8549.66,6362.57 h69
  text "4.11" at 9533.72,6362.57 h69
  text "Core" at 10305.65,6362.57 h69
  text "Gnd-Plane - L4" at 5042.02,6251.16 h69
  text "(.GP2)" at 6382.46,6251.16 h69
  text "1.2mil" at 7040.09,6251.16 h69
  text "4.1mil" at 7777.73,6139.75 h69
  text "Isola 370HR" at 8549.66,6139.75 h69
  text "4.11" at 9533.72,6139.75 h69
  text "PrePreg" at 10305.65,6139.75 h69
  text "SEE 001svengprerelstackup18.pdf FOR CORRECT STACKUP INFORMATION" at -22,6041 h66
  text "Pwr Plane - L5" at 5042.02,6028.34 h69
  text "(.GP3)" at 6382.46,6028.34 h69
  text "1.2mil" at 7040.09,6028.34 h69
  text "6mil" at 7777.73,5916.93 h69
  text "Isola 370HR" at 8549.66,5916.93 h69
  text "4.11" at 9533.72,5916.93 h69
  text "Core" at 10305.65,5916.93 h69
  text "Signals - L6" at 5042.02,5805.51 h69
  text "(.G2)" at 6382.46,5805.51 h69
  text "0.6mil" at 7040.09,5805.51 h69
  text "6.7mil" at 7777.73,5694.1 h69
  text "Isola 370HR" at 8549.66,5694.1 h69
  text "4.11" at 9533.72,5694.1 h69
  text "PrePreg" at 10305.65,5694.1 h69
  text "Gnd-Plane - L7" at 5042.02,5582.69 h69
  text "(.GP4)" at 6382.46,5582.69 h69
  text "1.2mil" at 7040.09,5582.69 h69
  text "4mil" at 7777.73,5471.28 h69
  text "Rogers RO4350" at 8549.66,5471.28 h69
  text "3.66" at 9533.72,5471.28 h69
  text "Core" at 10305.65,5471.28 h69
  text "Signals - L8" at 5042.02,5359.87 h69
  text "(.G3)" at 6382.46,5359.87 h69
  text "0.6mil" at 7040.09,5359.87 h69
  text "7.3mil" at 7777.73,5248.46 h69
  text "Rogers RO4350" at 8549.66,5248.46 h69
  text "3.66" at 9533.72,5248.46 h69
  text "PrePreg" at 10305.65,5248.46 h69
  text "Gnd-Plane - L9" at 5042.02,5137.05 h69
  text "(.GP5)" at 6382.46,5137.05 h69
  text "1.2mil" at 7040.09,5137.05 h69
  text "4mil" at 7777.73,5025.64 h69
  text "Rogers RO4350" at 8549.66,5025.64 h69
  text "3.66" at 9533.72,5025.64 h69
  text "Core" at 10305.65,5025.64 h69
  text "Bottom Layer - L10" at 5042.02,4914.23 h69
  text "(.GBL)" at 6382.46,4914.23 h69
  text "0.6mil" at 7040.09,4914.23 h69
  text "Bottom Solder Mask" at 5042.02,4691.41 h69
  text "(.GBS)" at 6382.46,4691.41 h69
  text "0.4mil" at 7777.73,4691.41 h69
  text "Solder Resist" at 8549.66,4691.41 h69
  text "3.50" at 9533.72,4691.41 h69
  text ".Layer_Name" at 601,-858.49 h60
M13 Component Bodies Top:
  text ".Layer_Name" at 601,-858.49 h60
M14 Component Bodies Bottom:
  text ".Layer_Name" at 601,-858.49 h60
M15 Courtyards Top:
  text ".Layer_Name" at 601,-858.49 h60
M16 Courtyards Bottom:
  text ".Layer_Name" at 601,-858.49 h60
Drill Drawing:
  text ".legend" at 8950.5,725.5 h60
  text "Drill Table" at 8975.5,540.5 h60
  text ".Layer_Name" at 601,-858.49 h60

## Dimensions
0,0 to 0,2680 on M2 Board Dimensions
0,0 to 8833,0 on M2 Board Dimensions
